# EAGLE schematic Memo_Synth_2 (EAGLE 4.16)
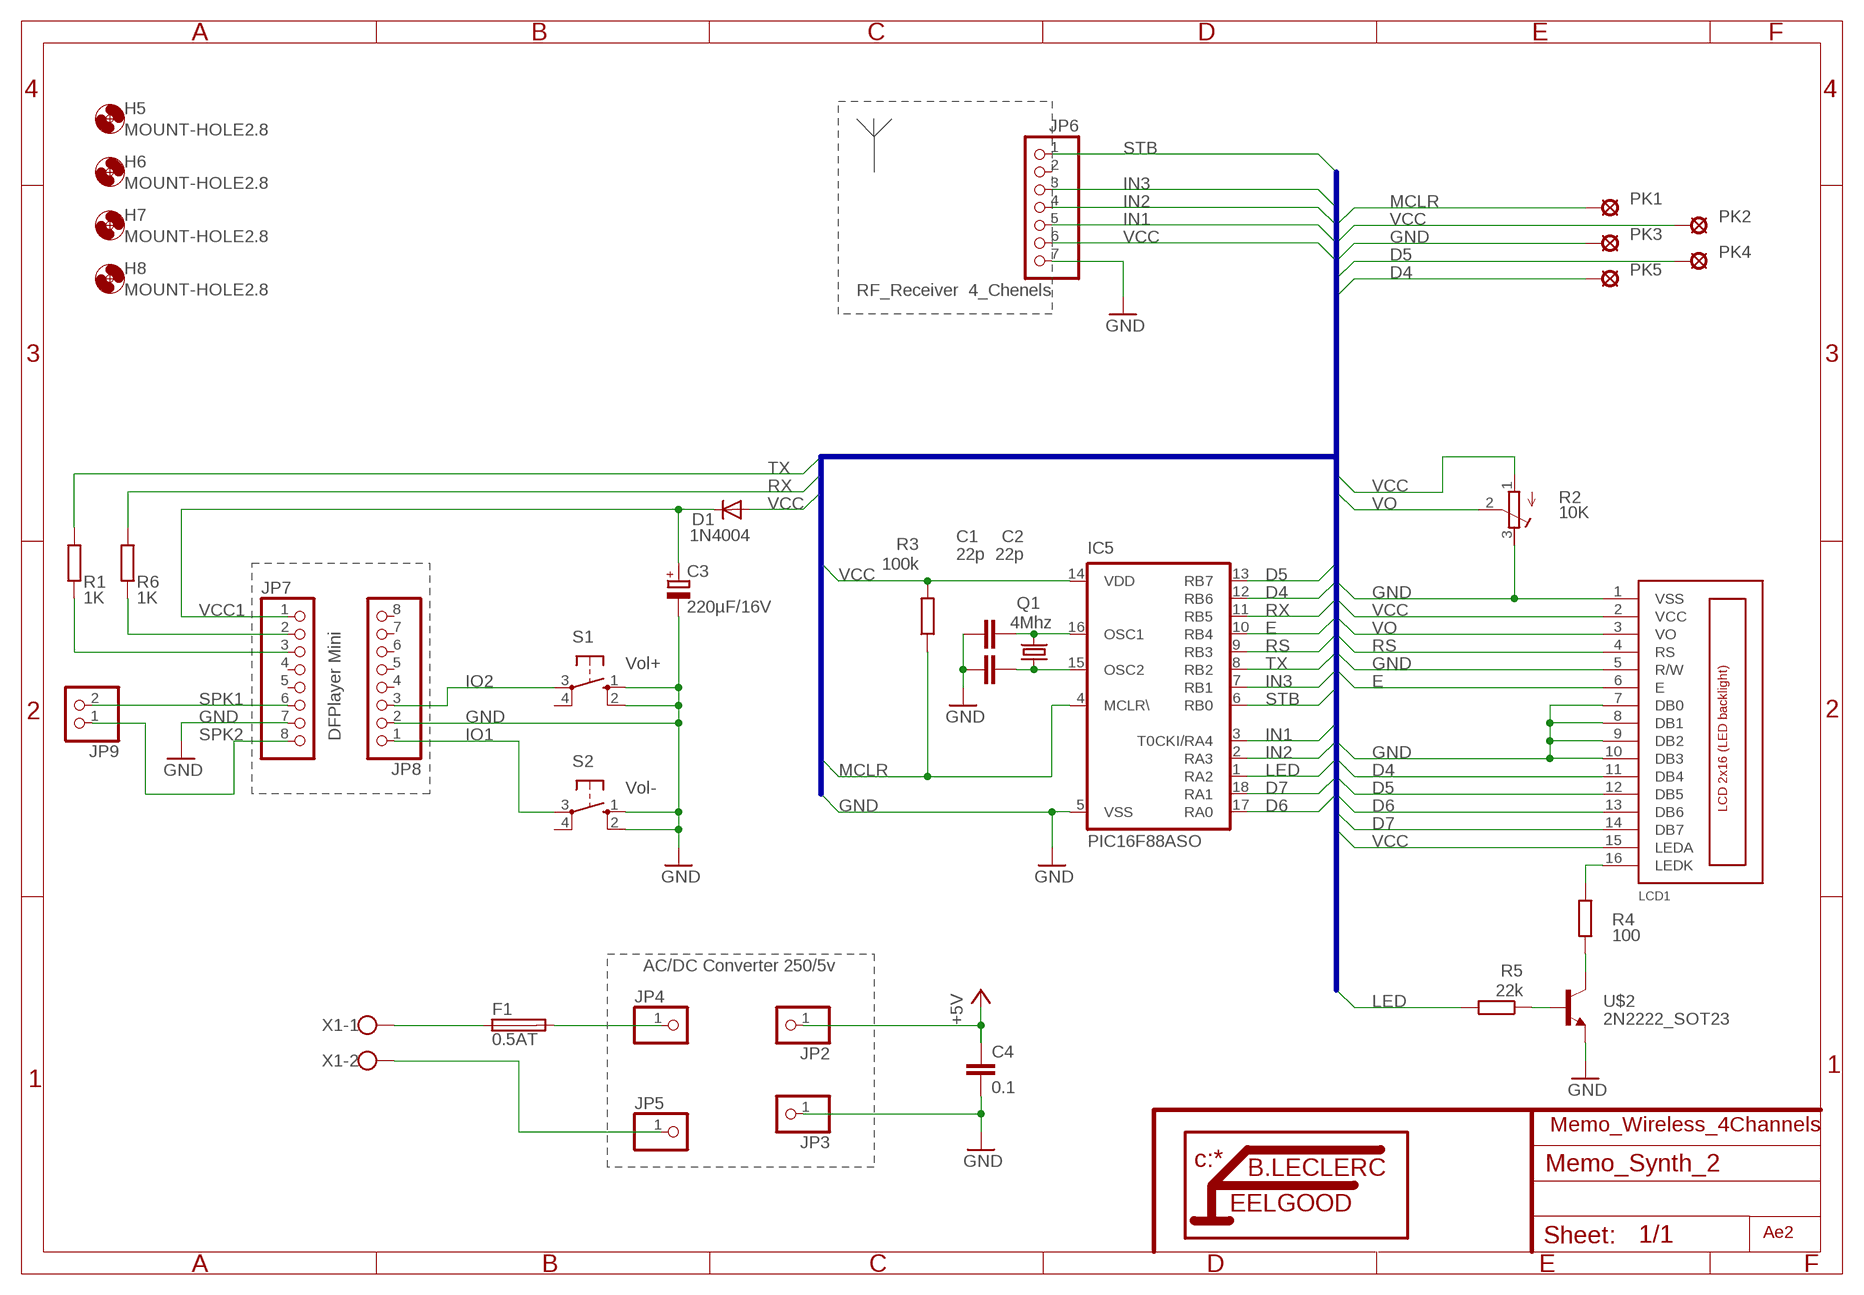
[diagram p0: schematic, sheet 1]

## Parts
C1  22p  C-EUC1206  [C1206]
C2  22p  C-EUC1206  [C1206]
C3  220µF/16V  CPOL-EUE2.5-7  [E2,5-7]
C4  0.1  C-EUC1206  [C1206]
D1  1N4004  [DO41-10]
F1  0.5AT  FUSESH22,5  [SH22,5]
H5  MOUNT-HOLE2.8  [2,8]
H6  MOUNT-HOLE2.8  [2,8]
H7  MOUNT-HOLE2.8  [2,8]
H8  MOUNT-HOLE2.8  [2,8]
IC5  PIC16F88ASO  PIC16F84ASO  [SO-18W]
JP2  PINHD-1X1  [1X01]
JP3  PINHD-1X1  [1X01]
JP4  PINHD-1X1  [1X01]
JP5  PINHD-1X1  [1X01]
JP6  PINHD-1X7  [1X07]
JP7  PINHD-1X8  [1X08]
JP8  PINHD-1X8  [1X08]
JP9  PINHD-1X2  [1X02]
LCD1  LCD_2X16_SIL  [HY-1602F]
PK1  SE14  [SE14]
PK2  SE14  [SE14]
PK3  SE14  [SE14]
PK4  SE14  [SE14]
PK5  SE14  [SE14]
Q1  4Mhz  CRYTALSM49  [SM49]
R1  1K  R-EU_M1206  [M1206]
R2  10K  R-TRIMM3103  [RTRIM3103]
R3  100k  R-EU_M1206  [M1206]
R4  100  R-EU_M1206  [M1206]
R5  22k  R-EU_M1206  [M1206]
R6  1K  R-EU_M1206  [M1206]
S1  10-XX  [B3F-10XX]
S2  10-XX  [B3F-10XX]
U$2  2N2222_SOT23  [SOT23-BEC]
X1  W237-2N  [W237-2N]

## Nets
D4: IC5.12(RB6) LCD1.11(DB4) PK5.MP
D5: IC5.13(RB7) LCD1.12(DB5) PK4.MP
D6: IC5.17(RA0) LCD1.13(DB6)
D7: IC5.18(RA1) LCD1.14(DB7)
E: IC5.10(RB4) LCD1.6(E)
GND: C1.1 C2.1 C3.- C4.2 IC5.5(VSS) JP3.1 JP6.7 JP7.7 JP8.2 LCD1.1(VSS) LCD1.5(R/W) LCD1.7(DB0) LCD1.8(DB1) LCD1.9(DB2) LCD1.10(DB3) PK3.MP R2.3(A) S1.1(S) S1.2(S1) S2.1(S) S2.2(S1) U$2.E
IN1: IC5.3(T0CKI/RA4) JP6.5
IN2: IC5.2(RA3) JP6.4
IN3: IC5.7(RB1) JP6.3
IO1: JP8.1 S2.3(P)
IO2: JP8.3 S1.3(P)
LED: IC5.1(RA2) R5.2
MCLR: IC5.4(MCLR\) PK1.MP R3.1
N$1: C1.2 IC5.16(OSC1) Q1.2
N$2: C2.2 IC5.15(OSC2) Q1.1
N$3: R4.1 U$2.C
N$4: JP7.3 R1.1
N$5: JP7.2 R6.1
N$6: LCD1.16(LEDK) R4.2
N$7: F1.1 X1.1
N$8: F1.2 JP4.1
N$9: R5.1 U$2.B
N$10: JP5.1 X1.2
RS: IC5.9(RB3) LCD1.4(RS)
RX: IC5.11(RB5) R6.2
SPK1: JP7.6 JP9.2
SPK2: JP7.8 JP9.1
STB: IC5.6(RB0) JP6.1
TX: IC5.8(RB2) R1.2
VCC: C4.1 D1.A IC5.14(VDD) JP2.1 JP6.6 LCD1.2(VCC) LCD1.15(LEDA) PK2.MP R2.1(E) R3.2 ; supply symbol labelled +5V
VCC1: C3.+ D1.C JP7.1
VO: LCD1.3(VO) R2.2(S)
Unconnected: JP6.2 JP7.4 JP7.5 JP8.4 JP8.5 JP8.6 JP8.7 JP8.8 S1.4(P1) S2.4(P1)

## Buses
B$1

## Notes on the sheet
- RF_Receiver  4_Chenels
- Vol+
- DFPlayer Mini
- Vol-
- AC/DC Converter 250/5v
- Memo_Wireless_4Channels
- Ae2

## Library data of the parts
C1 C2 C4 = rcl:C-EU: CAPACITOR, European symbol
C3 = rcl:CPOL-EU: POLARIZED CAPACITOR, European symbol
D1 = diode:1N4004: DIODE
F1 = fuse:FUSE: Fuse
H5-H8 = holes:MOUNT-HOLE: MOUNTING HOLE with drill center marker
IC5 = microchip:PIC16F8*: MICROCONTROLLER 8-Bit PIC16F8X Family - CMOS Flash/EEPROM Pin Compatible : PIC16F83, PIC16CR83, PIC16F84A, PIC16CR84 see also PIC16C*
JP2-JP5 = pinhead:PINHD-1X1: PIN HEADER
JP6 = pinhead:PINHD-1X7: PIN HEADER
JP7 JP8 = pinhead:PINHD-1X8: PIN HEADER
JP9 = pinhead:PINHD-1X2: PIN HEADER
LCD1 = lcd_2x16_led_backlight:LCD_2X16_SIL
PK1-PK5 = solpad:SE14: SOLDER PAD
Q1 = crystal:CRYTAL: CRYSTAL
R1 R3-R6 = rcl:R-EU_: RESISTOR, European symbol
R2 = rcl:R-TRIMM: Trimm resistor
S1 S2 = switch-omron:10-XX: OMRON SWITCH
U$2 = transistor:2N2222_SOT23
X1 = con-wago-508:W237-2N: WAGO SREW CLAMP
